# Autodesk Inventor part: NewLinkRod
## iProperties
Shininess: 0.0
Length Units: 11269
Angle Units: 11279
Time Units: 11290
Mass Units: 11283
Length Display Precision: 3
Angle Display Precision: 2
Compacted: True
Created: 2000-12
Part Number: NewLinkRod
Document SubType Name: Modeling
Designer: Administrator
Density: 1 g/cm^3
Description: ROD, LINK
Density: 0.0
Volumn: 0.0
Area: 0.0
PropertySet Name: Model Information
Control State: 0
Master: False
Checked Out: False
Author: Administrator
Revision Number: A
